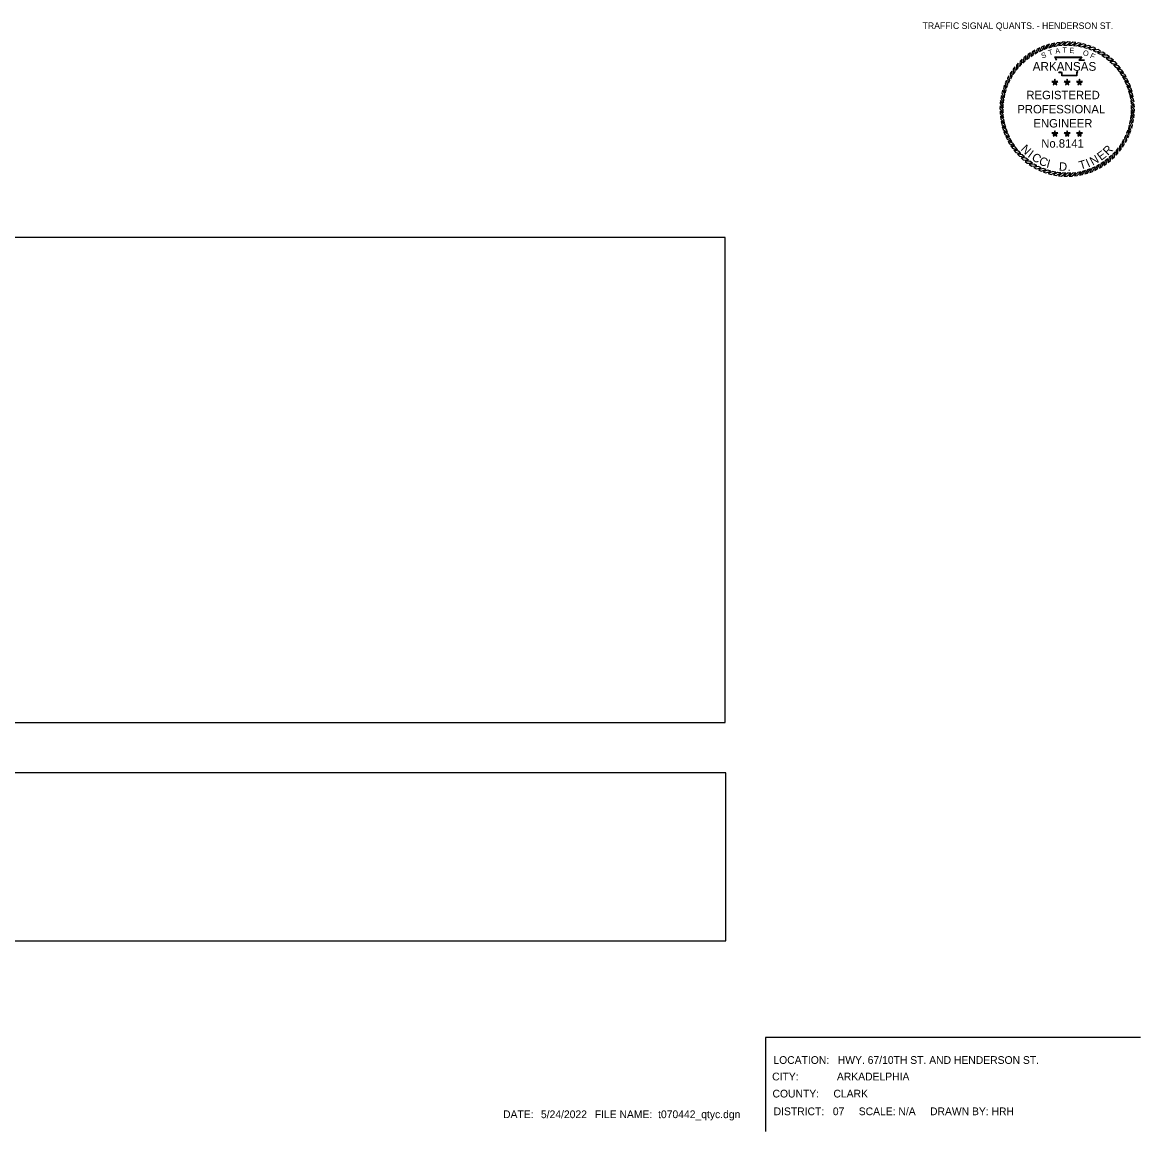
# Model space of a CAD drawing. Extents: x 418532 to 419834, y -565899 to -565296.
# Drawn here: x 419227 to 419834, y -565899 to -565296 of the extents above; entities that cross this region are included whole.
import ezdxf

# ---------------------------------------------------------------- set-up
doc = ezdxf.new("R2010")
doc.units = 0
for name, color, linetype in [('1', 7, 'Continuous'), ('G-ANNO-SYMB', 7, 'Continuous'), ('Level 10', 7, 'Continuous'), ('Level 57', 7, 'Continuous'), ('V-SIGNAL-LOOP', 7, 'Continuous')]:
    doc.layers.add(name, color=color, linetype=linetype)

msp = doc.modelspace()

# ---------------------------------------------------------------- linework, layer by layer
at = {"layer": 'G-ANNO-SYMB'}
for points in [[(419779.4, -565310.29), (419777.98, -565310.96), (419776.8, -565313.5), (419778.28, -565312.68)], [(419782.06, -565309.22), (419780.59, -565309.78), (419779.21, -565312.21), (419780.76, -565311.52)], [(419784.79, -565308.37), (419783.28, -565308.81), (419781.72, -565311.13), (419783.31, -565310.55)], [(419787.58, -565307.73), (419786.05, -565308.05), (419784.3, -565310.24), (419785.94, -565309.79)], [(419790.41, -565307.31), (419788.86, -565307.51), (419786.95, -565309.56), (419788.62, -565309.24)], [(419793.27, -565307.12), (419791.7, -565307.19), (419789.64, -565309.08), (419791.33, -565308.9)], [(419796.13, -565307.15), (419794.57, -565307.1), (419792.36, -565308.82), (419794.06, -565308.77)], [(419798.99, -565307.4), (419797.43, -565307.23), (419795.1, -565308.78), (419796.79, -565308.86)], [(419801.81, -565307.88), (419800.27, -565307.59), (419797.82, -565308.95), (419799.51, -565309.16)], [(419804.59, -565308.58), (419803.07, -565308.17), (419800.53, -565309.33), (419802.19, -565309.67)], [(419807.3, -565309.49), (419805.83, -565308.96), (419803.2, -565309.92), (419804.83, -565310.39)], [(419809.94, -565310.62), (419808.51, -565309.97), (419805.81, -565310.72), (419807.4, -565311.32)], [(419769.84, -565316.53), (419768.7, -565317.61), (419768.36, -565320.38), (419769.52, -565319.14)], [(419772.04, -565314.69), (419770.82, -565315.68), (419770.26, -565318.42), (419771.51, -565317.27)], [(419774.37, -565313.03), (419773.08, -565313.92), (419772.31, -565316.61), (419773.65, -565315.57)], [(419776.83, -565311.56), (419775.47, -565312.34), (419774.49, -565314.96), (419775.91, -565314.03)], [(419812.47, -565311.94), (419811.1, -565311.19), (419808.35, -565311.73), (419809.89, -565312.45)], [(419814.9, -565313.47), (419813.59, -565312.61), (419810.81, -565312.93), (419812.28, -565313.76)], [(419817.2, -565315.17), (419815.96, -565314.22), (419813.16, -565314.31), (419814.57, -565315.27)], [(419819.36, -565317.06), (419818.19, -565316), (419815.4, -565315.88), (419816.72, -565316.94)], [(419765.91, -565320.69), (419764.95, -565321.93), (419765.05, -565324.73), (419766, -565323.32)], [(419767.79, -565318.53), (419766.74, -565319.69), (419766.62, -565322.49), (419767.68, -565321.16)], [(419821.36, -565319.1), (419820.28, -565317.96), (419817.51, -565317.62), (419818.74, -565318.78)], [(419823.2, -565321.3), (419822.21, -565320.08), (419819.47, -565319.52), (419820.61, -565320.78)], [(419824.86, -565323.64), (419823.97, -565322.34), (419821.28, -565321.57), (419822.32, -565322.91)], [(419761.35, -565327.95), (419760.71, -565329.38), (419761.46, -565332.08), (419762.06, -565330.49)], [(419762.68, -565325.41), (419761.93, -565326.79), (419762.46, -565329.54), (419763.18, -565328)], [(419764.2, -565322.99), (419763.35, -565324.3), (419763.66, -565327.08), (419764.5, -565325.61)], [(419787.64, -565329.05), (419787.27, -565328.54), (419786.06, -565328.54), (419787.04, -565329.25)], [(419787.64, -565329.05), (419788.02, -565328.54), (419787.64, -565327.38), (419787.27, -565328.54)], [(419787.64, -565329.05), (419788.25, -565329.25), (419789.23, -565328.54), (419788.02, -565328.54)], [(419794.31, -565329.05), (419793.94, -565328.54), (419792.73, -565328.54), (419793.71, -565329.25)], [(419794.31, -565329.05), (419794.69, -565328.54), (419794.31, -565327.38), (419793.94, -565328.54)], [(419794.31, -565329.05), (419794.92, -565329.25), (419795.9, -565328.54), (419794.69, -565328.54)], [(419800.98, -565329.05), (419800.61, -565328.54), (419799.4, -565328.54), (419800.38, -565329.25)], [(419800.98, -565329.05), (419801.36, -565328.54), (419800.98, -565327.38), (419800.61, -565328.54)], [(419800.98, -565329.05), (419801.59, -565329.25), (419802.57, -565328.54), (419801.36, -565328.54)], [(419826.33, -565326.09), (419825.55, -565324.73), (419822.93, -565323.75), (419823.86, -565325.17)], [(419827.6, -565328.66), (419826.93, -565327.24), (419824.39, -565326.06), (419825.21, -565327.55)], [(419828.67, -565331.32), (419828.11, -565329.85), (419825.68, -565328.47), (419826.37, -565330.02)], [(419759.32, -565333.3), (419758.91, -565334.81), (419760.07, -565337.36), (419760.41, -565335.7)], [(419760.23, -565330.59), (419759.7, -565332.06), (419760.66, -565334.69), (419761.13, -565333.06)], [(419787.64, -565329.05), (419787.04, -565329.25), (419786.66, -565330.4), (419787.64, -565329.69)], [(419787.64, -565329.05), (419787.64, -565329.69), (419788.62, -565330.4), (419788.25, -565329.25)], [(419794.31, -565329.05), (419793.71, -565329.25), (419793.33, -565330.4), (419794.31, -565329.69)], [(419794.31, -565329.05), (419794.31, -565329.69), (419795.29, -565330.4), (419794.92, -565329.25)], [(419800.98, -565329.05), (419800.38, -565329.25), (419800, -565330.4), (419800.98, -565329.69)], [(419800.98, -565329.05), (419800.98, -565329.69), (419801.96, -565330.4), (419801.59, -565329.25)], [(419829.52, -565334.05), (419829.08, -565332.55), (419826.76, -565330.98), (419827.34, -565332.58)], [(419830.16, -565336.84), (419829.84, -565335.31), (419827.65, -565333.57), (419828.1, -565335.2)], [(419758.14, -565338.9), (419757.97, -565340.46), (419759.51, -565342.79), (419759.59, -565341.1)], [(419758.62, -565336.08), (419758.33, -565337.62), (419759.68, -565340.06), (419759.9, -565338.38)], [(419830.58, -565339.68), (419830.38, -565338.12), (419828.33, -565336.21), (419828.65, -565337.88)], [(419830.77, -565342.53), (419830.7, -565340.97), (419828.81, -565338.91), (419828.99, -565340.59)], [(419757.88, -565341.75), (419757.84, -565343.32), (419759.56, -565345.53), (419759.51, -565343.83)], [(419757.85, -565344.62), (419757.93, -565346.18), (419759.82, -565348.25), (419759.63, -565346.56)], [(419830.49, -565348.25), (419830.66, -565346.69), (419829.11, -565344.36), (419829.03, -565346.05)], [(419830.74, -565345.4), (419830.79, -565343.83), (419829.07, -565341.63), (419829.12, -565343.32)], [(419758.05, -565347.48), (419758.25, -565349.03), (419760.29, -565350.94), (419759.98, -565349.27)], [(419758.47, -565350.31), (419758.79, -565351.84), (419760.98, -565353.58), (419760.53, -565351.95)], [(419759.1, -565353.1), (419759.55, -565354.61), (419761.86, -565356.17), (419761.29, -565354.57)], [(419828.4, -565356.57), (419828.92, -565355.09), (419827.97, -565352.46), (419827.5, -565354.09)], [(419829.31, -565353.85), (419829.72, -565352.34), (419828.56, -565349.79), (419828.22, -565351.45)], [(419830.01, -565351.07), (419830.3, -565349.53), (419828.94, -565347.09), (419828.73, -565348.77)], [(419759.96, -565355.83), (419760.52, -565357.3), (419762.95, -565358.68), (419762.25, -565357.13)], [(419761.03, -565358.49), (419761.7, -565359.91), (419764.23, -565361.09), (419763.42, -565359.61)], [(419787.64, -565356.98), (419787.27, -565356.47), (419786.06, -565356.47), (419787.04, -565357.18)], [(419787.64, -565356.98), (419787.04, -565357.18), (419786.66, -565358.33), (419787.64, -565357.62)], [(419787.64, -565356.98), (419788.02, -565356.47), (419787.64, -565355.31), (419787.27, -565356.47)], [(419787.64, -565356.98), (419788.25, -565357.18), (419789.23, -565356.47), (419788.02, -565356.47)], [(419787.64, -565356.98), (419787.64, -565357.62), (419788.62, -565358.33), (419788.25, -565357.18)], [(419794.31, -565356.98), (419793.94, -565356.47), (419792.73, -565356.47), (419793.71, -565357.18)], [(419794.31, -565356.98), (419793.71, -565357.18), (419793.33, -565358.33), (419794.31, -565357.62)], [(419794.31, -565356.98), (419794.69, -565356.47), (419794.31, -565355.31), (419793.94, -565356.47)], [(419794.31, -565356.98), (419794.92, -565357.18), (419795.9, -565356.47), (419794.69, -565356.47)], [(419794.31, -565356.98), (419794.31, -565357.62), (419795.29, -565358.33), (419794.92, -565357.18)], [(419800.98, -565356.98), (419800.61, -565356.47), (419799.4, -565356.47), (419800.38, -565357.18)], [(419800.98, -565356.98), (419800.38, -565357.18), (419800, -565358.33), (419800.98, -565357.62)], [(419800.98, -565356.98), (419801.36, -565356.47), (419800.98, -565355.31), (419800.61, -565356.47)], [(419800.98, -565356.98), (419801.59, -565357.18), (419802.57, -565356.47), (419801.36, -565356.47)], [(419800.98, -565356.98), (419800.98, -565357.62), (419801.96, -565358.33), (419801.59, -565357.18)], [(419825.95, -565361.74), (419826.7, -565360.36), (419826.16, -565357.62), (419825.44, -565359.15)], [(419827.27, -565359.2), (419827.91, -565357.77), (419827.17, -565355.07), (419826.57, -565356.66)], [(419762.3, -565361.06), (419763.08, -565362.42), (419765.7, -565363.4), (419764.77, -565361.98)], [(419763.77, -565363.51), (419764.66, -565364.81), (419767.34, -565365.58), (419766.3, -565364.24)], [(419820.83, -565368.62), (419821.88, -565367.46), (419822.01, -565364.66), (419820.95, -565365.99)], [(419822.72, -565366.46), (419823.67, -565365.22), (419823.58, -565362.43), (419822.62, -565363.83)], [(419824.42, -565364.16), (419825.28, -565362.85), (419824.96, -565360.07), (419824.12, -565361.54)], [(419765.43, -565365.85), (419766.41, -565367.07), (419769.15, -565367.63), (419768.01, -565366.38)], [(419767.27, -565368.05), (419768.34, -565369.19), (419771.12, -565369.53), (419769.88, -565368.37)], [(419769.27, -565370.09), (419770.43, -565371.15), (419773.23, -565371.27), (419771.9, -565370.21)], [(419814.25, -565374.12), (419815.55, -565373.23), (419816.32, -565370.55), (419814.98, -565371.58)], [(419816.59, -565372.46), (419817.81, -565371.48), (419818.37, -565368.74), (419817.11, -565369.88)], [(419818.79, -565370.62), (419819.93, -565369.55), (419820.27, -565366.77), (419819.11, -565368.01)], [(419771.43, -565371.98), (419772.67, -565372.93), (419775.46, -565372.84), (419774.06, -565371.89)], [(419773.73, -565373.69), (419775.04, -565374.54), (419777.82, -565374.23), (419776.35, -565373.39)], [(419776.15, -565375.21), (419777.53, -565375.96), (419780.27, -565375.43), (419778.74, -565374.7)], [(419778.69, -565376.54), (419780.12, -565377.18), (419782.82, -565376.43), (419781.23, -565375.83)], [(419781.32, -565377.66), (419782.8, -565378.19), (419785.43, -565377.23), (419783.8, -565376.76)], [(419801.05, -565379.42), (419802.58, -565379.1), (419804.32, -565376.91), (419802.69, -565377.36)], [(419803.84, -565378.79), (419805.34, -565378.34), (419806.91, -565376.03), (419805.31, -565376.6)], [(419806.57, -565377.93), (419808.04, -565377.37), (419809.41, -565374.94), (419807.87, -565375.63)], [(419809.23, -565376.86), (419810.65, -565376.19), (419811.83, -565373.66), (419810.34, -565374.47)], [(419811.79, -565375.59), (419813.16, -565374.81), (419814.13, -565372.19), (419812.72, -565373.12)], [(419784.04, -565378.57), (419785.55, -565378.98), (419788.1, -565377.82), (419786.44, -565377.48)], [(419786.82, -565379.27), (419788.36, -565379.56), (419790.8, -565378.21), (419789.12, -565377.99)], [(419789.64, -565379.75), (419791.2, -565379.92), (419793.53, -565378.37), (419791.84, -565378.3)], [(419792.49, -565380.01), (419794.06, -565380.05), (419796.26, -565378.33), (419794.57, -565378.38)], [(419795.36, -565380.04), (419796.92, -565379.96), (419798.98, -565378.07), (419797.3, -565378.25)], [(419798.21, -565379.84), (419799.77, -565379.64), (419801.68, -565377.6), (419800.01, -565377.91)]]:
    msp.add_lwpolyline(points, close=True, dxfattribs=at)
for points in [[(419788.47, -565317.1), (419787.62, -565315.26), (419802.33, -565315.25), (419801.1, -565316.8), (419802.1, -565316.78), (419802.94, -565316.77), (419803.77, -565316.86)], [(419788.68, -565317), (419787.98, -565315.49), (419801.85, -565315.49), (419800.61, -565317.04), (419802.1, -565317.02), (419802.93, -565317.01), (419803.75, -565317.1)], [(419800.01, -565323.27), (419799.76, -565323.47), (419799.68, -565323.78), (419799.6, -565324.54), (419799.6, -565325.56), (419791.38, -565325.56), (419791.38, -565324.18), (419791.38, -565323.88), (419791.05, -565323.78), (419789.88, -565323.78), (419789.67, -565323.46)], [(419799.87, -565323.09), (419799.56, -565323.34), (419799.45, -565323.73), (419799.36, -565324.53), (419799.36, -565325.32), (419791.62, -565325.32), (419791.62, -565324.18), (419791.62, -565323.71), (419791.08, -565323.54), (419790.01, -565323.54), (419789.87, -565323.33)]]:
    msp.add_lwpolyline(points, dxfattribs=at)
at = {"layer": 'Level 57'}
for points in [[(419630.59, -565847.55), (419630.59, -565898.75)], [(419834.17, -565847.55), (419630.59, -565847.55)]]:
    msp.add_lwpolyline(points, dxfattribs=at)
at = {"layer": 'V-SIGNAL-LOOP'}
for points in [[(419150.56, -565676.69), (419608.6, -565676.69), (419608.6, -565413.21), (419150.56, -565413.21)], [(419150.37, -565795.13), (419609.12, -565795.13), (419609.12, -565703.99), (419150.37, -565703.99)]]:
    msp.add_lwpolyline(points, close=True, dxfattribs=at)

# ---------------------------------------------------------------- texts
at = {"layer": '1'}
msp.add_text('TRAFFIC SIGNAL QUANTS. - HENDERSON ST.', height=3.5172, rotation=360, dxfattribs=at).set_placement((419715.85, -565300.02))
at = {"layer": 'G-ANNO-SYMB'}
for s, height, rotation, p in [('A', 2.9, 8.67877, (419788.02, -565313.56)), ('T', 2.9, 1.47887, (419791.77, -565312.98)), ('E', 2.9, 356.67203, (419795.48, -565313.07)), ('S', 2.9, 19.77256, (419780.81, -565316.14)), ('T', 2.9, 16.90148, (419784.5, -565314.48)), ('O', 2.9, 341.2218, (419802.53, -565314.07)), ('F', 2.9, 335.36282, (419806.44, -565315.6)), ('N', 4.59, 315.26758, (419768.83, -565365.57)), ('R', 4.59, 45.47796, (419816.4, -565368.98)), ('I', 4.59, 324.21406, (419772.56, -565369.27)), ('C', 4.59, 328.68731, (419774.63, -565370.89)), ('C', 4.59, 336.51548, (419778.54, -565373.31)), ('I', 4.59, 344.34365, (419782.73, -565375.18)), ('T', 4.59, 16.77466, (419801.49, -565376.47)), ('I', 4.59, 24.23006, (419805.7, -565375.26)), ('N', 4.59, 28.7033, (419808.13, -565374.27)), ('E', 4.59, 37.64979, (419812.74, -565371.75)), ('D', 4.59, 356.64507, (419789.73, -565376.93)), ('.', 4.59, 4.84601, (419794.54, -565377.24))]:
    msp.add_text(s, height=height, rotation=rotation, dxfattribs=at).set_placement(p)
for s, height, p in [('ARKANSAS', 4.737, (419775.59, -565322.74)), ('REGISTERED', 4.585, (419772.15, -565338.2)), ('PROFESSIONAL', 4.5855, (419767.24, -565345.87)), ('ENGINEER', 4.585, (419775.97, -565353.54)), ('No.8141', 4.567, (419780.25, -565364.47))]:
    msp.add_text(s, height=height, dxfattribs=at).set_placement(p)
at = {"layer": 'Level 10'}
for s, p in [('LOCATION:   HWY. 67/10TH ST. AND HENDERSON ST.', (419634.85, -565861.97)), ('CITY:', (419634.17, -565870.93)), (' ARKADELPHIA', (419667.77, -565870.93)), ('COUNTY:     CLARK', (419634.37, -565880.2)), ('DATE:  ', (419488.12, -565891.43)), ('5/24/2022', (419508.67, -565891.43)), ('  FILE NAME: ', (419534.76, -565891.43)), ('t070442_qtyc.dgn', (419572.26, -565891.43)), ('DISTRICT:   07     SCALE: N/A     DRAWN BY: HRH', (419634.98, -565889.83))]:
    msp.add_text(s, height=4.2, rotation=360, dxfattribs=at).set_placement(p)

doc.saveas('drawing.dxf')
